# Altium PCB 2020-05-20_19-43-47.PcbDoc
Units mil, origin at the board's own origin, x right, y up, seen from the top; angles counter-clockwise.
Board outline 3000 x 3000 mil, 4 copper layers (Top Layer, MidLayer1, MidLayer2, Bottom Layer); 17 components, 8 nets, 36 pads, 40 vias.
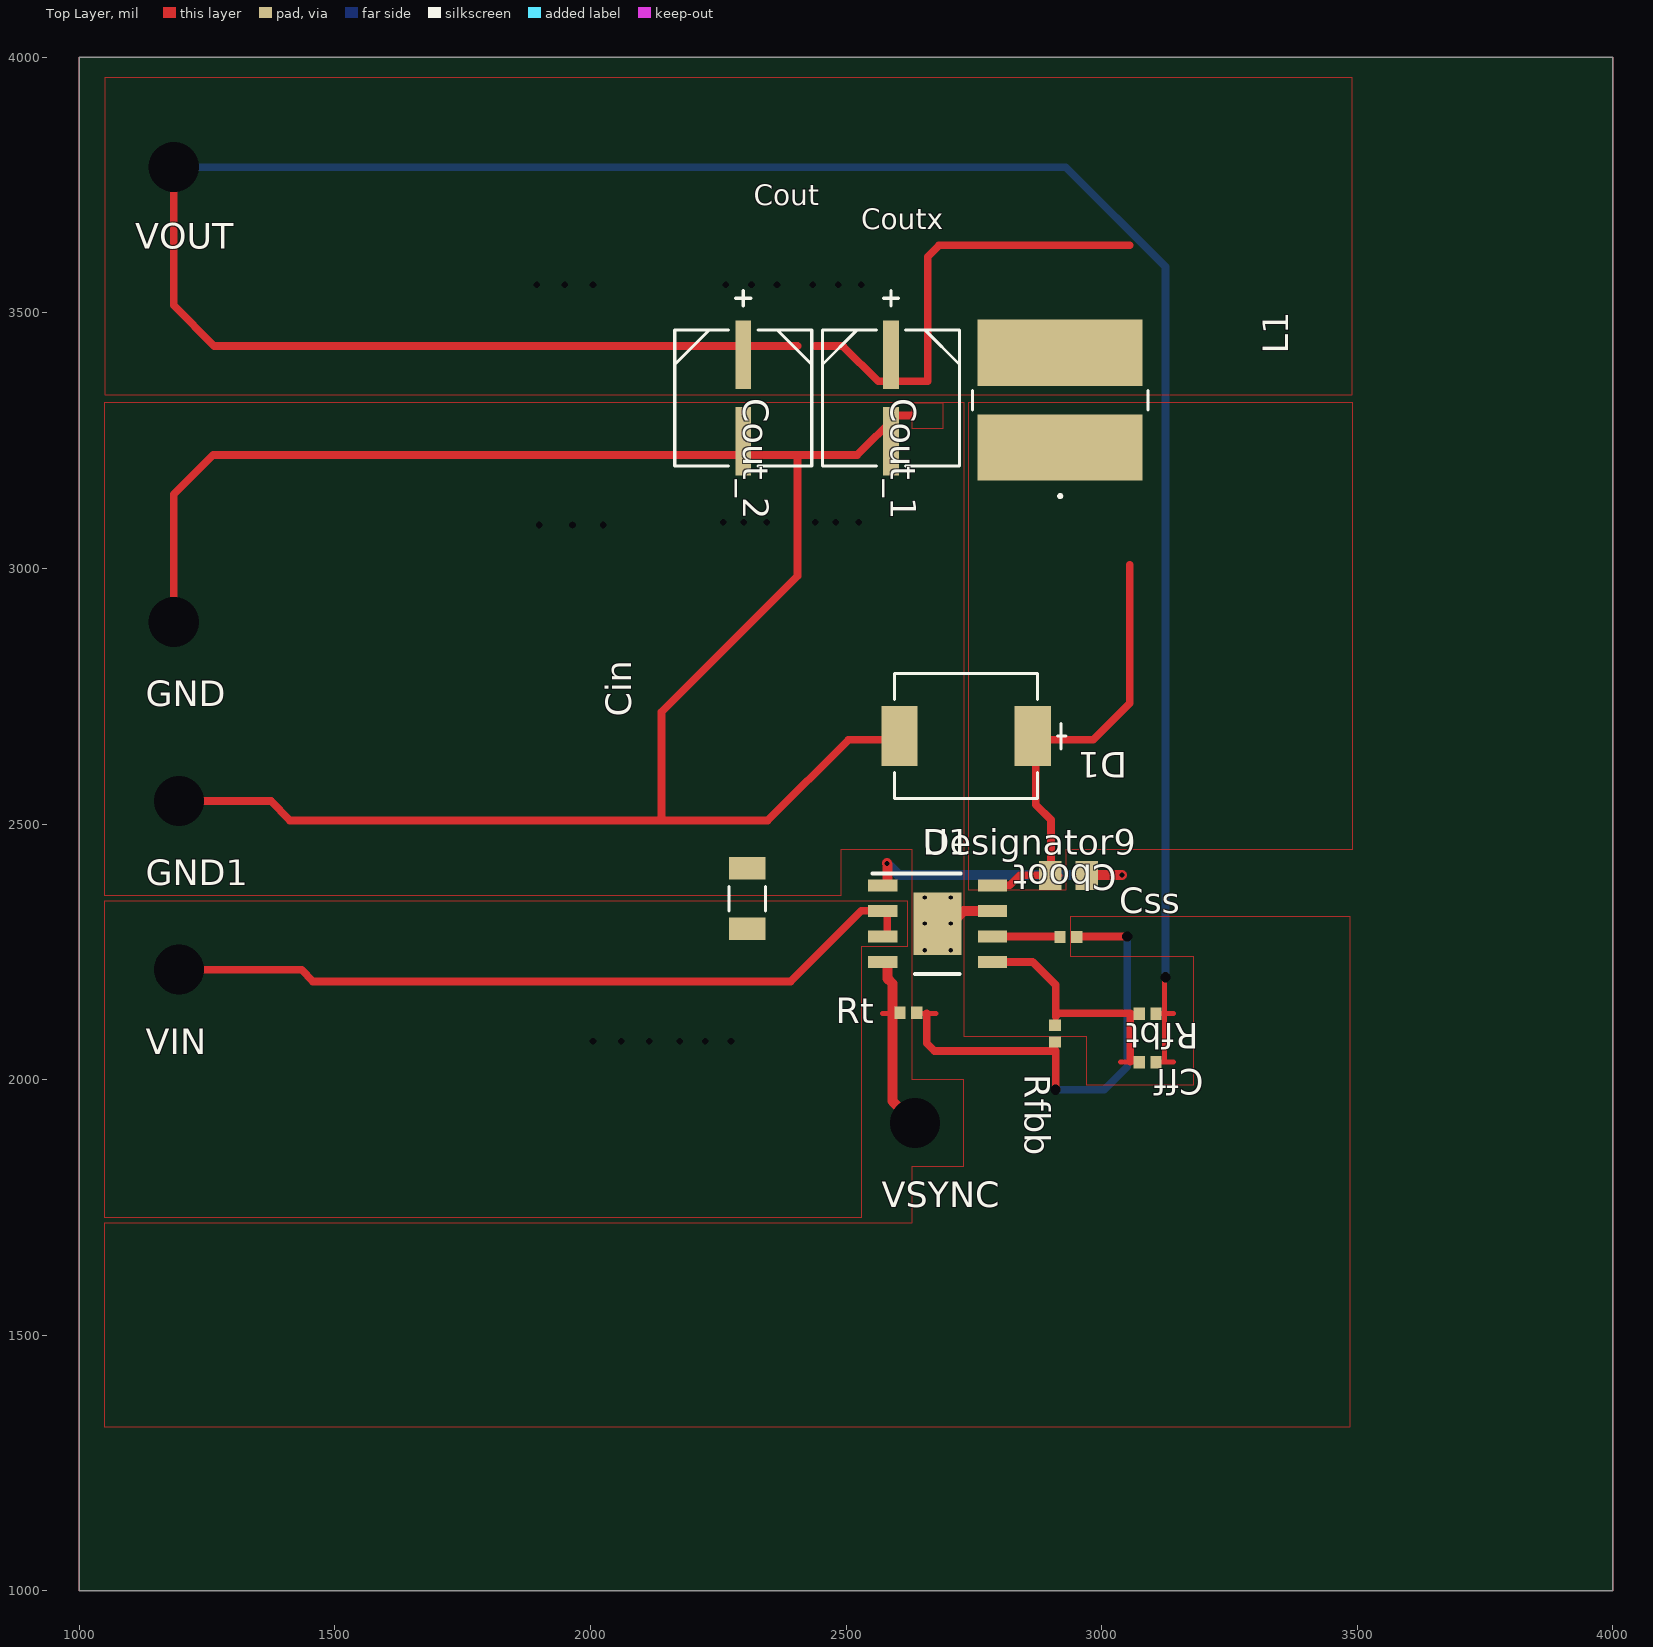
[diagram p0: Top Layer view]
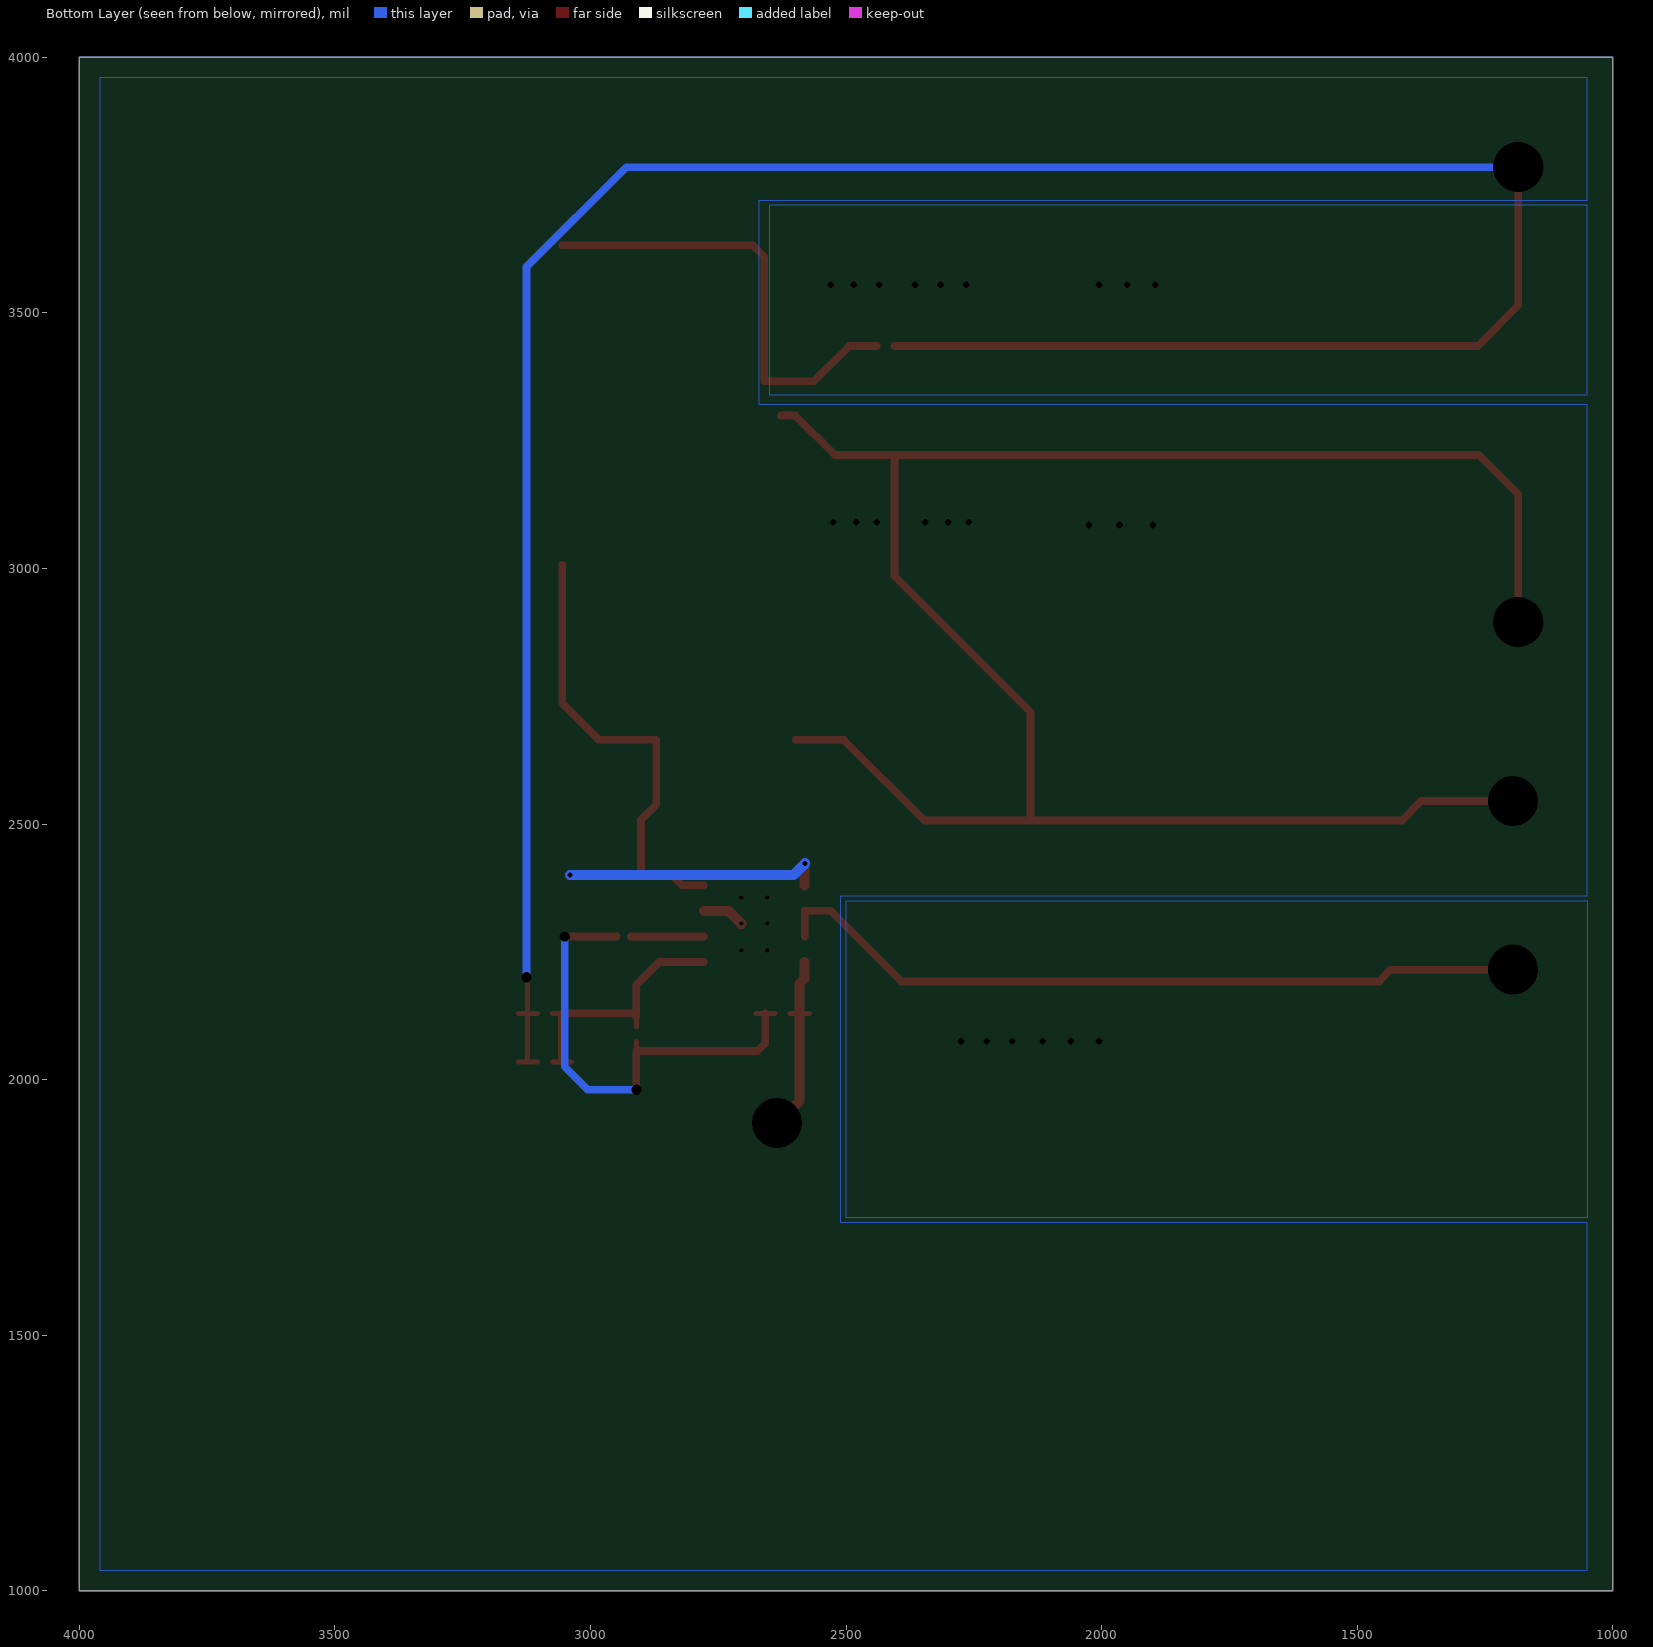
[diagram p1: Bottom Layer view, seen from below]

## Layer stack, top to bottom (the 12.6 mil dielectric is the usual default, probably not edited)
Top Layer: signal copper 1.4
Dielectric: core 12.6, FR-4, Dk 4.8
MidLayer1: signal copper 1.4
Dielectric: prepreg 12.6, FR-4, Dk 4.8
MidLayer2: signal copper 1.4
Dielectric: core 12.6, FR-4, Dk 4.8
Bottom Layer: signal copper 1.4

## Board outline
1000,1000 4000,1000 4000,4000 1000,4000

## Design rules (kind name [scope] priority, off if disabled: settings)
PlaneConnect [All] p0: scope1count=1 scope1_0_kind=Board scope1_0_value=Board scope2count=1 scope2_0_kind=Board scope2_0_value=Board commentlength=0 planeconnectstyle=Direct reliefexpansion=20 reliefentries=4 reliefconductorwidth=10 reliefairgap=10
PlaneConnect [All] p1: planeconnectstyle=Direct reliefexpansion=20 reliefentries=4 reliefconductorwidth=10 reliefairgap=10
PolygonConnect [All] p0: scope1count=1 scope1_0_kind=Board scope1_0_value=Board scope2count=1 scope2_0_kind=Board scope2_0_value=Board commentlength=0 connectstyle=Direct reliefconductorwidth=10 reliefentries=4 polygonreliefangle="90 Angle"
PolygonConnect [All] p1: connectstyle=Direct reliefconductorwidth=10 reliefentries=4 polygonreliefangle="90 Angle"

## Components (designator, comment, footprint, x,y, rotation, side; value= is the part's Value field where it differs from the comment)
Cboot "" 0805 2935,2399 r180 top
Cff "" 0402 3090,2034 r180 top
Cin "" 1206 2307,2354 r90 top
Cout_1 "" CAPSMT_62_F61 2588,3333 r270 top
Cout_2 "" CAPSMT_62_F61 2299,3333 r270 top
Css "" 0402 2935,2279 r0 top
D1 "" SMC 2735,2672 r180 top
GND "" TP-1502 1185,2894 r0 top
GND1 "" TP-1502 1194,2543 r0 top
L1 "" VLP8040 2919,3329 r90 top
Rfbb "" 0402 2909,2090 r270 top
Rfbt "" 0402 3090,2129 r180 top
Rt "" 0402 2622,2131 r0 top
U1 "" DDA0008E_N 2679,2305 r0 top
VIN "" TP-1502 1194,2214 r0 top
VOUT "" TP-1502 1185,3784 r0 top
VSYNC "" TP-1502 2633,1913 r0 top

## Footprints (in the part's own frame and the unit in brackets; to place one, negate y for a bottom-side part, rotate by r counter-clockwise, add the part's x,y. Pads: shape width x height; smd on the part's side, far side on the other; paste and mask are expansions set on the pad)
0402 [mil]
  rect 22x24 smd: 1(-16.5,0) 2(16.5,0)
0805 [mil]
  rect 44x57 smd: 1(-35.5,0) 2(35.5,0)
1206 [mil]
  rect 44x71 smd: 1(-59,0) 2(59,0)
  silkscreen extent -24,-36 24,36
CAPSMT_62_F61 [mil]
  rect 134x31 smd: 1(-84.5,0) 2(84.5,0)
  silkscreen extent -210,-134 133,134
DDA0008E_N [mm]
  rect 1.45x0.6 smd: 1(-2.725,1.905) 2(-2.725,0.635) 3(-2.725,-0.635) 4(-2.725,-1.905) 5(2.725,-1.905) 6(2.725,-0.635) 7(2.725,0.635) 8(2.725,1.905)
  rect 2.4x3.1 smd: 9(0,0)
  silkscreen extent -3.22,-2.5 1.15,2.5
SMC [mil]
  rect 71x117 smd: 1(-130.5,0) 2(130.5,0)
  silkscreen extent -196,-123 140,123
TP-1502 [mil]
  round 65 / inner round 0 / far side round 65 hole 32: 1(0,0)
VLP8040 [mil]
  rect 130x323 smd: 1(-92.5,0) 2(92.5,0)
  silkscreen extent -190,-172 19,172

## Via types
v1: diameter 0, hole 13, Top Layer to Bottom Layer, 24 vias
v2: diameter 0, hole 8, Top Layer to Bottom Layer, 6 vias
v3: diameter 0, hole 98, Top Layer to Bottom Layer, 5 vias
v4: diameter 0, hole 20, Top Layer to Bottom Layer, 3 vias
v5: diameter 0, hole 10, Top Layer to Bottom Layer, 2 vias

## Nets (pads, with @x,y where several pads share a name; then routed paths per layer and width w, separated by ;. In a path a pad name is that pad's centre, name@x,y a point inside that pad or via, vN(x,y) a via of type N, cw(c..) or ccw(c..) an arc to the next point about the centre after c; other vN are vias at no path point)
0: Cin.2 Cout_1.2 Cout_2.2 Css.2 D1.2 GND1.1 GND.1 Rfbb.2 Rt.2 U1.7 U1.9 | length 5167.7
  Top Layer w10: Rt.2@2639,2129.5 2676,2129.5 ; 2909.5,2037 Rfbb.2@2909.5,2074 ; Css.2@2949,2279.5 2986,2279.5
  Top Layer w15: v3(1185,2895) 1185,3145 1262,3222 2405,3222 ; v3(1195,2545) 1375,2545 1412,2507 2139,2507 ; D1.2@2598,2665 2505,2665 2347,2507 2139,2507 ; 2627,3299 2599,3299 2522,3222 2405,3222 ; 2658,2130 2658,2071 2673,2056 2910,2056 v4(2910,1980) ; Css.2@2949,2280 2968,2280 v4(3050,2280) ; 2139,2507 2139,2719 2405,2985 2405,3222
  Top Layer w20: v2(2705,2305) 2730,2330 U1.7@2778,2330
  Bottom Layer w15: v4(2910,1980) 3005,1980 3050,2025 v4(3050,2280)
  other v1: 1900,3085 1965,3085 2025,3085 2260,3090 2300,3090 2345,3090 2440,3090 2480,3090 2525,3090
  other v2: 2654,2253 2705,2253 2654,2305 2654,2356 2705,2356
1: Cff.1 Cout_1.1 Cout_2.1 L1.2 Rfbt.1 VOUT.1 | length 6070.7
  Top Layer w10: Cff.1@3104,2034.5 3141,2034.5 ; Rfbt.1@3104,2129.5 3141,2129.5 ; 3123,2035 3123,2130 3123,2198 v4(3125,2200)
  Top Layer w15: v3(1185,3785) 1185,3515 1264,3435 2405,3435 ; 2440,3435 2494,3435 2563,3366 2660,3366 2660,3610 2682,3632 3055,3632
  Bottom Layer w15: v3(1185,3785) 2930,3785 3125,3590 v4(3125,2200)
  other v1: 1895,3555 1950,3555 2005,3555 2265,3555 2315,3555 2365,3555 2435,3555 2485,3555 2530,3555
3: Cin.1 U1.2 U1.3 VIN.1 | length 1502
  Top Layer w15: v3(1195,2215) 1435,2215 1457,2192 2139,2192 ; 2140,2192 2392,2192 2530,2330 2581,2330 U1.3@2581,2280
  other v1: 2005,2075 2060,2075 2115,2075 2175,2075 2225,2075 2275,2075
5: Cff.2 Rfbb.1 Rfbt.2 U1.5 | length 567.9
  Top Layer w10: Rfbb.1@2909.5,2104 2909.5,2141 ; 3037,2034.5 Cff.2@3074,2034.5 ; 3037,2129.5 Rfbt.2@3074,2129.5
  Top Layer w15: U1.5@2778,2230 2865,2230 2910,2185 2910,2123 2916,2130 3056,2130 3056,2035
6: Cboot.2 D1.1 L1.1 U1.8 | length 930.1
  Top Layer w10: Cboot.2@2882,2399.5 Cboot.2@2919,2399.5
  Top Layer w15: U1.8@2778,2380 2820,2380 2840,2400 2901,2400 2901,2508 2871,2538 2871,2665 2984,2665 3055,2736 3055,3007
7: Css.1 U1.6 | length 180
  Top Layer w10: 2882,2279.5 Css.1@2919,2279.5
  Top Layer w15: U1.6@2778,2280 2897,2280 Css.1@2921,2280
9: Cboot.1 U1.1 | length 621.8
  Top Layer w10: Cboot.1@2949,2399.5 Cboot.1@2986,2399.5
  Top Layer w20: v5(2580,2423) 2581,2421 U1.1@2581,2380 ; Cboot.1@2968,2400 v5(3040,2400)
  Bottom Layer w20: v5(2580,2423) 2603,2400 v5(3040,2400)
14: Rt.1 U1.4 VSYNC.1 | length 374.7
  Top Layer w10: 2572,2129.5 Rt.1@2609,2129.5
  Top Layer w20: U1.4@2581,2230 2581,2198 2591,2188 2591,2130 2591,1958 v3(2635,1915)

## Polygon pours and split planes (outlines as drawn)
1 on Top Layer " " (solid, pour order 2): 1050,3340 3490,3340 3490,3960 1050,3960
3 on Top Layer " " (solid, pour order 3): 2620,2350 2620,2260 2530,2260 2530,1730 1050,1730 1050,2350
6 on Top Layer " " (solid, pour order 4): 2740,3325 3490,3325 3490,2450 2930,2450 2930,2370 2740,2370
0 on Top Layer " " (solid, pour order 5): 2630,3273 2630,3324 2689,3324 2689,3273
0 on Top Layer " " (solid, pour order 8): 1050,3325 2730,3325 2730,2085 2970,2085 2970,1990 3180,1990 3180,2080 3180,2240 2940,2240 2940,2320 3485,2320 3485,1320 1050,1320 1050,1720 2630,1720 2630,1830 2730,1830 2730,2000 2630,2000 2630,2450 2490,2450 2490,2360 1050,2360
1 on Bottom Layer " " (solid, pour order 0): 1050,3710 2650,3710 2650,3340 1050,3340
3 on Bottom Layer " " (solid, pour order 1): 1050,2350 1050,1730 2500,1730 2500,2350
0 on Bottom Layer " " (solid, pour order 7): 1050,3320 2670,3320 2670,3720 1050,3720 1050,3960 3960,3960 3960,1040 1050,1040 1050,1720 2510,1720 2510,2360 1050,2360
0 on MidLayer1 " " (solid, pour order 6): 1050,3960 3960,3960 3960,1040 1050,1040
0 on MidLayer2 " " (solid, pour order 9): 1050,3960 1050,1040 3960,1040 3960,3960

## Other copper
Multi-Layer:
  the board outline again, w1

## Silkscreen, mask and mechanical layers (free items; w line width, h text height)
Top Overlay:
  text "Cout" at 2320,3710 h40
  text "Coutx" at 2530,3663 h40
